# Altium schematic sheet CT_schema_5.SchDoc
size 300 x 247 mm
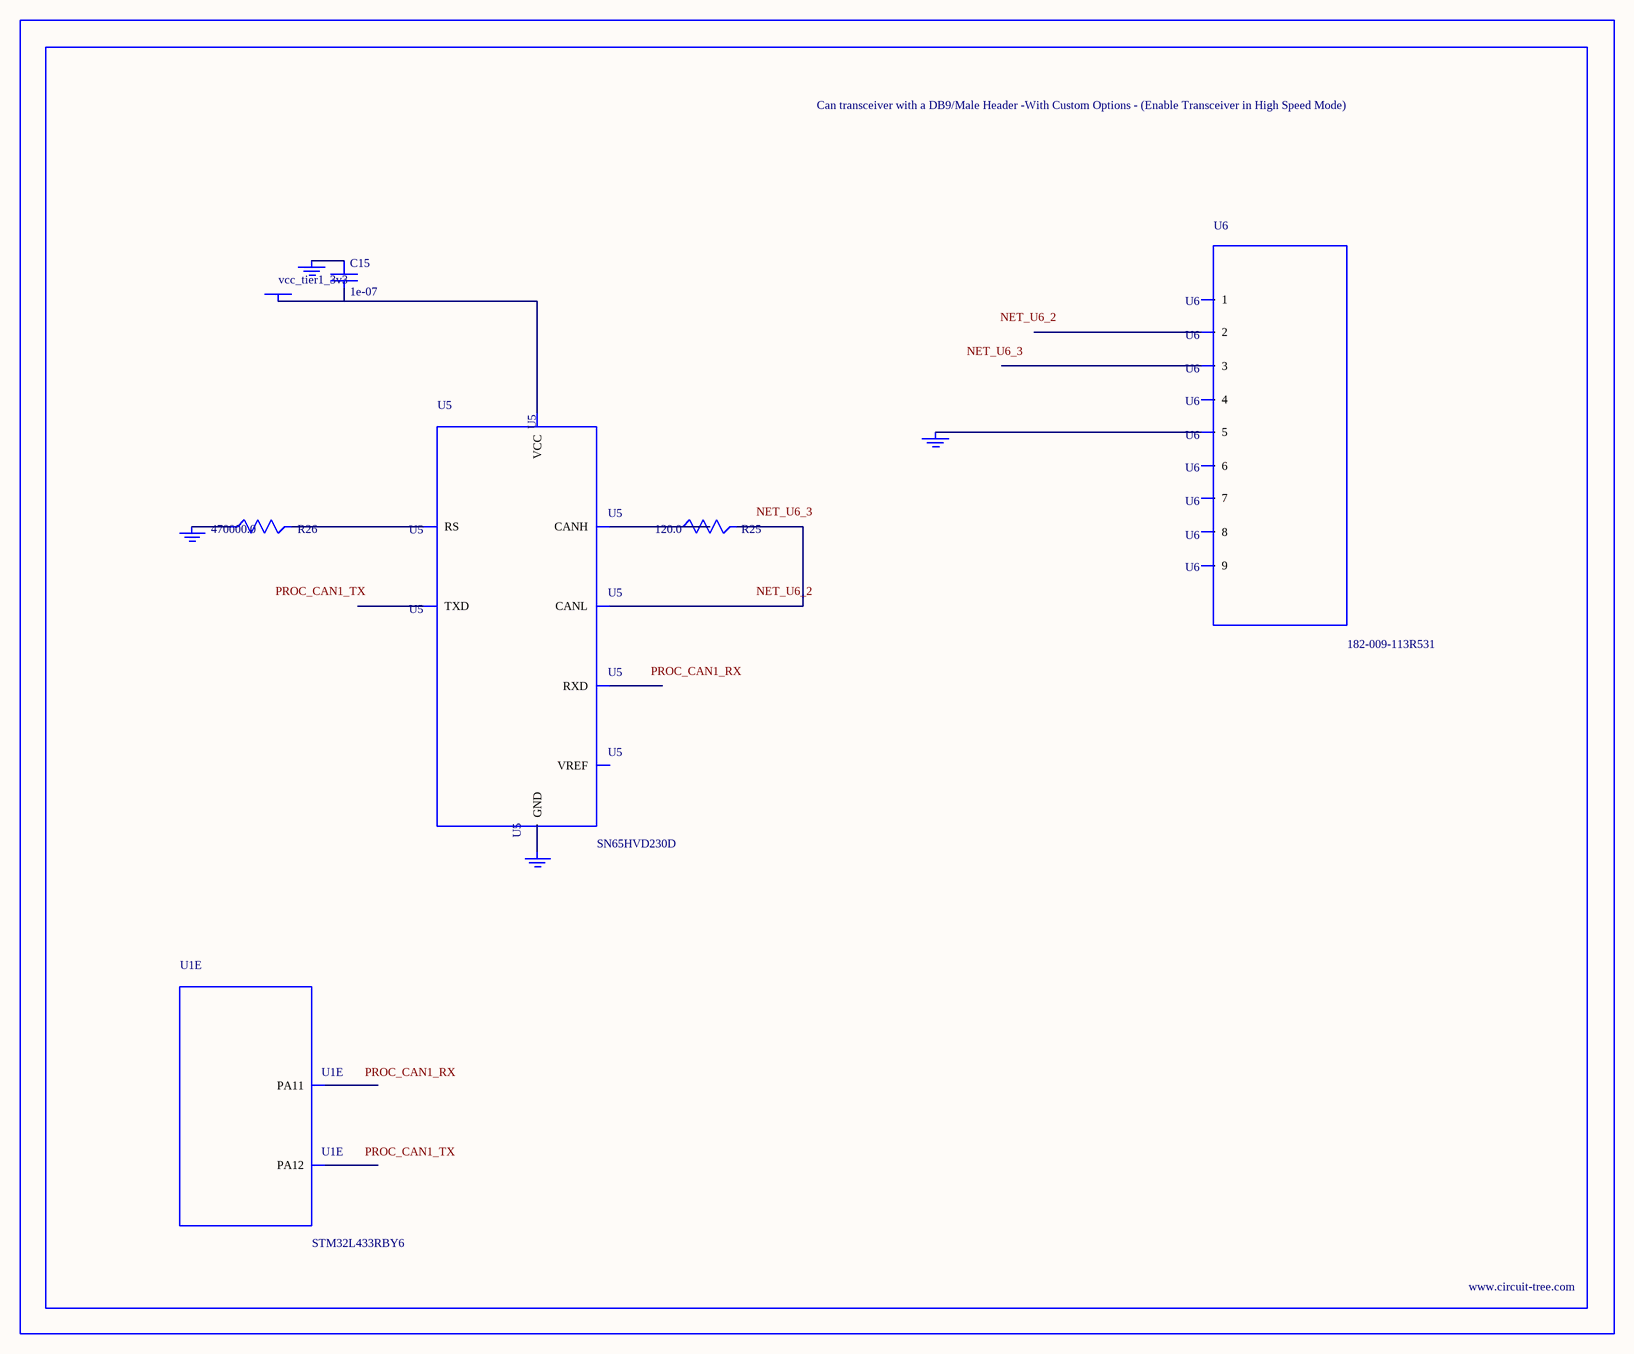
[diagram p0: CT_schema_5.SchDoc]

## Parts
BORDER4  (no value)
C15  1e-07  [C0402]
GND_INSTANCE_4_0  (no value)
GND_INSTANCE_4_1  (no value)
GND_INSTANCE_4_2  (no value)
GND_INSTANCE_4_3  (no value)
POWER_INSTANCE_4_0  vcc_tier1_3v3
R25  120.0  [R0603]
R26  470000.0  [R0603]
U1  STM32L433RBY6  [WLCSP64]  (part E of 6)
U5  SN65HVD230D  [SOIC-8]
U6  182-009-113R531  [182-009-MALE]

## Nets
NetC15_1: C15.1 GND_INSTANCE_4_0.0(GND)
NetC15_2: C15.2 POWER_INSTANCE_4_0.0(PWR) U5.3(VCC)
NetGND_INSTANCE_4_1_0: GND_INSTANCE_4_1.0(GND) R26.1
NetGND_INSTANCE_4_2_0: GND_INSTANCE_4_2.0(GND) U5.2(GND)
NetGND_INSTANCE_4_3_0: GND_INSTANCE_4_3.0(GND) U6.5
NetR25_1: R25.1 U5.7(CANH)
NetR25_2: R25.2 U5.6(CANL)
NetR26_2: R26.2 U5.8(RS)

Not connected (* = marked no-connect by the designer): U1 C1(PA12) D3(PA11); U5 1(TXD) 4(RXD) 5(VREF); U6 1 2 3 4 6 7 8 9

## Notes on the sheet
- Labels drawn without touching a wire or pin: NET_U6_2, NET_U6_3, PROC_CAN1_RX, PROC_CAN1_TX

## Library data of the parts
BORDER4 = BORDER_PAGE4
C15 = C0402C104K3RACTU
GND_INSTANCE_4_0-GND_INSTANCE_4_3 = GND
POWER_INSTANCE_4_0 = PWR
R25 = RC0603JR-07120RL
R26 = RC0603JR-07470KL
